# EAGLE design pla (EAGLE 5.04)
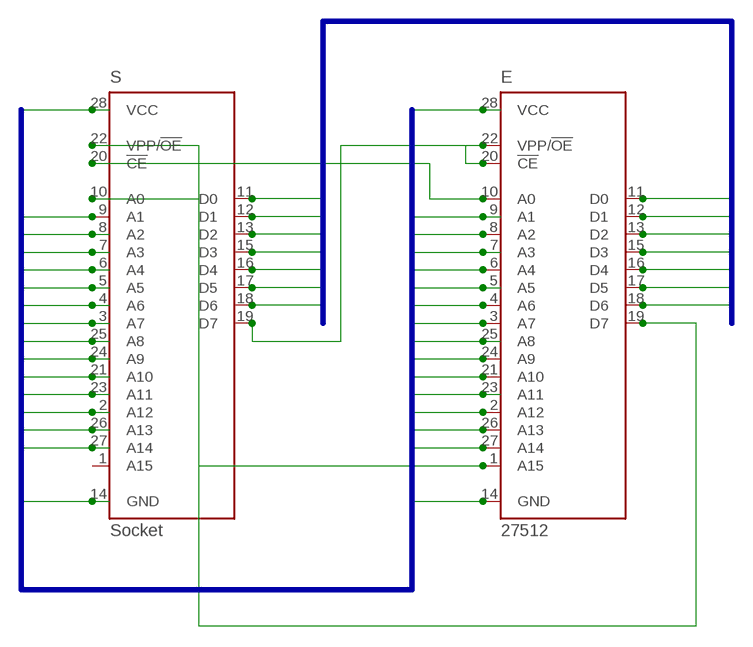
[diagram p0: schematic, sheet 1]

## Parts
E  27512  27C512AP  [DIL28-6]
S  Socket  27C512AP  [DIL28-6]

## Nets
A2: E.2(A12) S.2(A12)
A3: E.3(A7) S.3(A7)
A4: E.4(A6) S.4(A6)
A5: E.5(A5) S.5(A5)
A6: E.6(A4) S.6(A4)
A7: E.7(A3) S.7(A3)
A8: E.8(A2) S.8(A2)
A9: E.9(A1) S.9(A1)
A14: E.14(GND) S.14(GND)
A21: E.21(A10) S.21(A10)
A23: E.23(A11) S.23(A11)
A24: E.24(A9) S.24(A9)
A25: E.25(A8) S.25(A8)
A26: E.26(A13) S.26(A13)
A27: E.27(A14) S.27(A14)
A28: E.28(VCC) S.28(VCC)
B11: E.11(D0) S.11(D0)
B12: E.12(D1) S.12(D1)
B13: E.13(D2) S.13(D2)
B15: E.15(D3) S.15(D3)
B16: E.16(D4) S.16(D4)
B17: E.17(D5) S.17(D5)
B18: E.18(D6) S.18(D6)
N$1: E.20(!CE) E.22(VPP/!OE) S.19(D7)
N$2: E.1(A15) S.22(VPP/!OE)
N$3: E.10(A0) S.20(!CE)
N$4: E.19(D7) S.10(A0)
Unconnected: S.1(A15)

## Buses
B[11..19]
A[1..28]

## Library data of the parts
E S = microchip:27*512A: CMOS EPROM 512 K (64 K x 8)

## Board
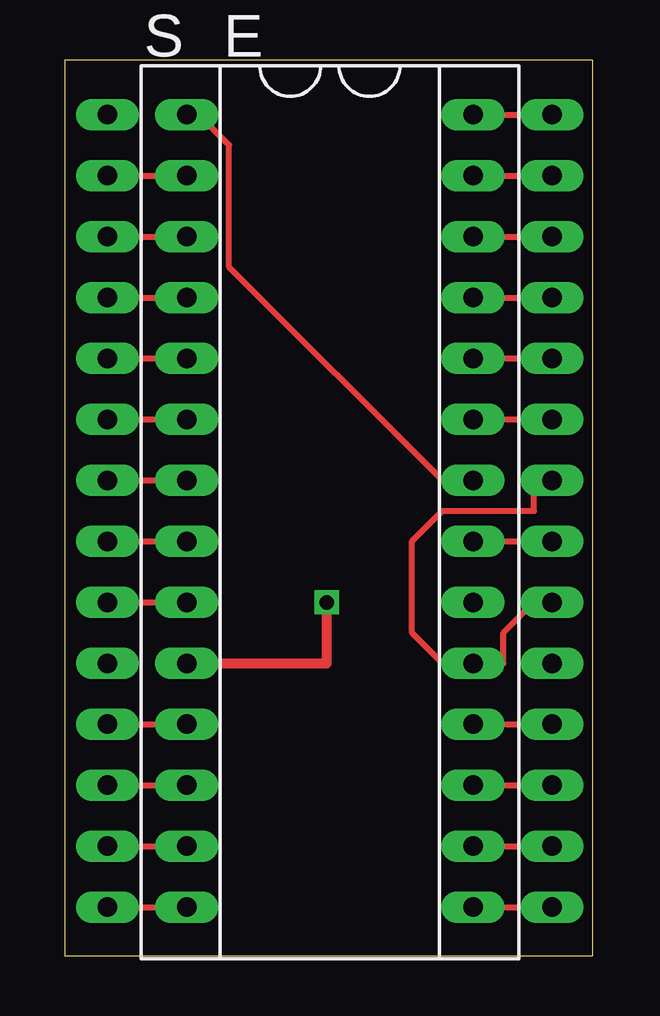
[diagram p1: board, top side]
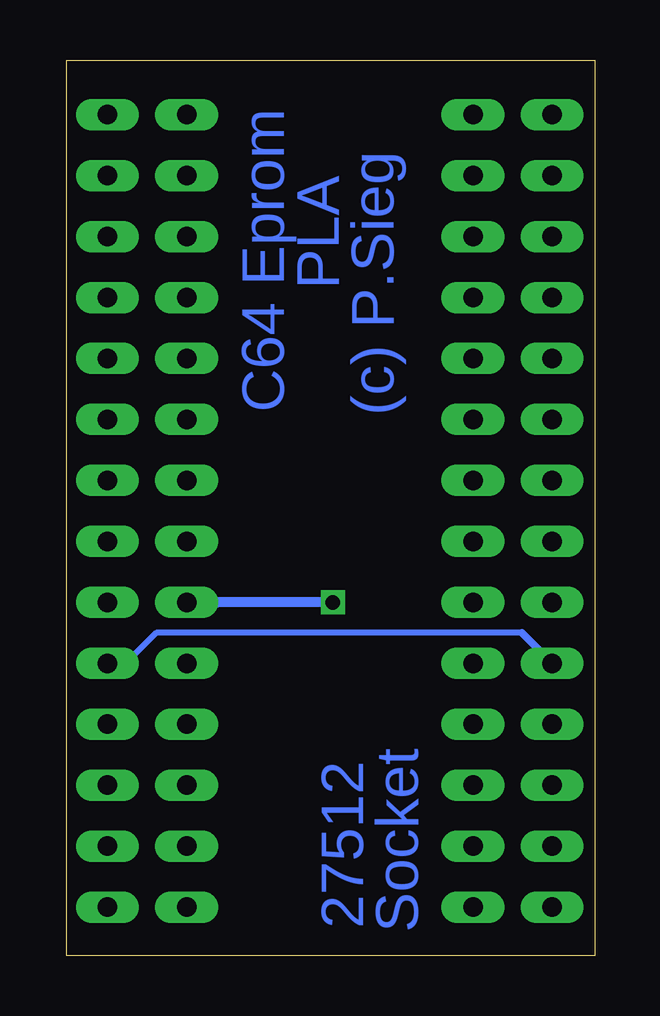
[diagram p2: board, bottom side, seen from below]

Size 22.02 x 37.33 mm. Coordinates in mm from the lower left corner, seen from the top.
Outline: 0,0 22.02,0 22.02,37.33 0,37.33 0,0
Copper layers (1*16): Top 0.035mm / dielectric 1.5mm / Bottom 0.035mm
Design rules "default": minimum track width 10mil, minimum drill 24mil, track to track 8mil, track to pad 8mil, pad to pad 8mil, via to via 8mil, smd to smd 8mil, copper to edge 40mil, drill to drill 8mil, minimum pad ring 10mil, minimum via ring 8mil, stop-mask expansion 4mil, vias tented up to drill 0mil, thermal gap 10mil

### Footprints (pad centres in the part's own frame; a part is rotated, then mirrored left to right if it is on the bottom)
DIL28-6 = drill 0.813 long: 1 -16.51,-7.62; 2 -13.97,-7.62; 3 -11.43,-7.62; 4 -8.89,-7.62; 5 -6.35,-7.62; 6 -3.81,-7.62; 7 -1.27,-7.62; 8 1.27,-7.62; 9 3.81,-7.62; 10 6.35,-7.62; 11 8.89,-7.62; 12 11.43,-7.62; 13 13.97,-7.62; 14 16.51,-7.62; 15 16.51,7.62; 16 13.97,7.62; 17 11.43,7.62; 18 8.89,7.62; 19 6.35,7.62; 20 3.81,7.62; 21 1.27,7.62; 22 -1.27,7.62; 23 -3.81,7.62; 24 -6.35,7.62; 25 -8.89,7.62; 26 -11.43,7.62; 27 -13.97,7.62; 28 -16.51,7.62

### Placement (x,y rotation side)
E  12.7,18.54 270 top
S  9.4,18.54 270 top

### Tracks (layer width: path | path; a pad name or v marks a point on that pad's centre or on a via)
A2
  Top 0.254: S.2 E.2
A3
  Top 0.254: S.3 E.3
A4
  Top 0.254: S.4 E.4
A5
  Top 0.254: S.5 E.5
A6
  Top 0.254: S.6 E.6
A7
  Top 0.254: S.7 E.7
A8
  Top 0.254: S.8 E.8
A9
  Top 0.254: S.9 E.9
A14
  Top 0.254: S.14 E.14
A21
  Top 0.254: S.21 E.21
A23
  Top 0.254: S.23 E.23
A24
  Top 0.254: S.24 E.24
A25
  Top 0.254: S.25 E.25
A26
  Top 0.254: S.26 E.26
A27
  Top 0.254: S.27 E.27
A28
  Top 0.254: S.28 E.28
B11
  Top 0.254: S.11 E.11
B12
  Top 0.254: S.12 E.12
B13
  Top 0.254: S.13 E.13
B15
  Top 0.254: S.15 E.15
B16
  Top 0.254: S.16 E.16
B17
  Top 0.254: S.17 E.17
B18
  Top 0.254: S.18 E.18
N$1
  Top 0.254: E.22 19.56,19.81 19.56,18.54 15.75,18.54 14.48,17.27 14.48,13.46 15.75,12.19 S.19 18.29,12.19 18.29,13.46 19.56,14.73 E.20
N$2
  Top 0.254: S.22 15.75,19.81 6.86,28.7 6.86,33.78 5.59,35.05 E.1
N$3  (via drill 0.6)
  Top 0.406: v10.92,14.73 10.92,12.19 E.10
  Bottom 0.254: E.10 4.32,12.19 | 15.75,14.73 S.20
  Bottom 0.406: v10.92,14.73 15.75,14.73
N$4
  Bottom 0.254: 3.05,13.46 18.29,13.46 19.56,12.19 E.19
  Bottom 0.305: 3.05,13.46 S.10

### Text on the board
Bottom: C64 Eprom | (c) P.Sieg | PLA | Socket | 27512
